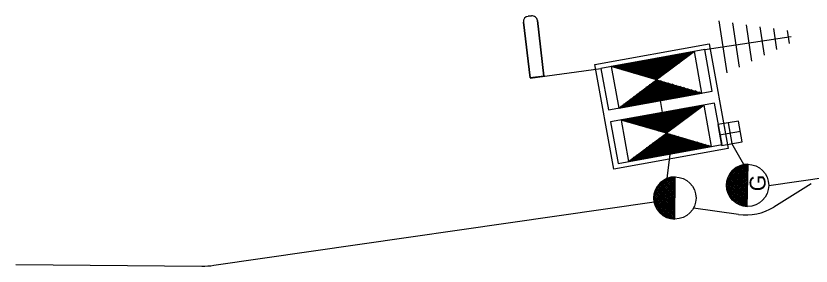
# Model space of a CAD drawing. Extents: x 584850 to 602551, y 145475 to 158627.
# Drawn here: x 585971.5 to 586122.2, y 156296.5 to 156344 of the extents above; entities that cross this region are included whole.
import ezdxf

# ---------------------------------------------------------------- set-up
doc = ezdxf.new("R2010")
doc.units = 0
doc.layers.add('Default', color=7, linetype='Continuous')

msp = doc.modelspace()

# ---------------------------------------------------------------- linework, layer by layer
at = {"layer": 'Default'}
for p, q in [((586106.26, 156333.18), (586104.77, 156343.04)), ((586108.62, 156334.29), (586107.35, 156342.67)), ((586110.98, 156335.4), (586109.94, 156342.31)), ((586113.34, 156336.51), (586112.52, 156341.94)), ((586115.7, 156337.62), (586115.1, 156341.58)), ((586118.06, 156338.73), (586117.69, 156341.21)), ((586102.04, 156337.59), (586118.4, 156340.05)), ((586094.13, 156332.78), (586096.81, 156336.64)), ((586094.74, 156333.23), (586097.14, 156336.7)), ((586095.35, 156333.69), (586097.47, 156336.76)), ((586095.95, 156334.14), (586097.81, 156336.82)), ((586096.56, 156334.6), (586098.14, 156336.88)), ((586098.18, 156335.81), (586096.95, 156336.66)), ((586097.17, 156335.05), (586098.48, 156336.94)), ((586098.38, 156335.96), (586097.28, 156336.72)), ((586098.58, 156336.11), (586097.62, 156336.78)), ((586097.77, 156335.51), (586098.81, 156337)), ((586098.79, 156336.26), (586097.95, 156336.84)), ((586098.99, 156336.42), (586098.29, 156336.9)), ((586098.38, 156335.96), (586099.14, 156337.06)), ((586099.19, 156336.57), (586098.62, 156336.97)), ((586099.39, 156336.72), (586098.95, 156337.03)), ((586098.99, 156336.42), (586099.48, 156337.12)), ((586099.6, 156336.87), (586099.29, 156337.09)), ((586099.6, 156336.87), (586099.81, 156337.18)), ((586099.8, 156337.02), (586099.62, 156337.15)), ((586100, 156337.18), (586099.96, 156337.21)), ((586087.33, 156333.5), (586088.46, 156335.12)), ((586087.57, 156333.43), (586088.79, 156335.18)), ((586087.82, 156333.36), (586089.12, 156335.24)), ((586088.06, 156333.28), (586089.46, 156335.3)), ((586088.3, 156333.21), (586089.79, 156335.36)), ((586088.54, 156333.14), (586090.13, 156335.42)), ((586093.12, 156332.02), (586088.6, 156335.15)), ((586088.79, 156333.07), (586090.46, 156335.48)), ((586093.32, 156332.17), (586088.94, 156335.21)), ((586089.03, 156333), (586090.79, 156335.55)), ((586089.27, 156332.93), (586091.13, 156335.61)), ((586093.52, 156332.32), (586089.27, 156335.27)), ((586089.52, 156332.86), (586091.46, 156335.67)), ((586093.73, 156332.47), (586089.6, 156335.33)), ((586089.76, 156332.79), (586091.8, 156335.73)), ((586093.93, 156332.62), (586089.94, 156335.39)), ((586090, 156332.72), (586092.13, 156335.79)), ((586090.24, 156332.65), (586092.46, 156335.85)), ((586094.13, 156332.78), (586090.27, 156335.45)), ((586090.49, 156332.58), (586092.8, 156335.91)), ((586094.33, 156332.93), (586090.61, 156335.51)), ((586090.73, 156332.5), (586093.13, 156335.97)), ((586094.54, 156333.08), (586090.94, 156335.57)), ((586090.97, 156332.43), (586093.47, 156336.03)), ((586091.22, 156332.36), (586093.8, 156336.09)), ((586094.74, 156333.23), (586091.27, 156335.63)), ((586091.46, 156332.29), (586094.13, 156336.15)), ((586094.94, 156333.38), (586091.61, 156335.69)), ((586091.7, 156332.22), (586094.47, 156336.21)), ((586091.94, 156332.15), (586094.8, 156336.27)), ((586095.14, 156333.53), (586091.94, 156335.75)), ((586092.19, 156332.08), (586095.14, 156336.33)), ((586095.34, 156333.69), (586092.27, 156335.81)), ((586092.43, 156332.01), (586095.47, 156336.39)), ((586095.55, 156333.84), (586092.61, 156335.87)), ((586092.67, 156331.94), (586095.8, 156336.45)), ((586092.92, 156331.87), (586096.14, 156336.51)), ((586095.75, 156333.99), (586092.94, 156335.94)), ((586095.95, 156334.14), (586093.28, 156336)), ((586093.52, 156332.32), (586096.47, 156336.58)), ((586096.15, 156334.29), (586093.61, 156336.06)), ((586096.36, 156334.44), (586093.94, 156336.12)), ((586096.56, 156334.6), (586094.28, 156336.18)), ((586096.76, 156334.75), (586094.61, 156336.24)), ((586096.96, 156334.9), (586094.95, 156336.3)), ((586097.17, 156335.05), (586095.28, 156336.36)), ((586097.37, 156335.2), (586095.61, 156336.42)), ((586097.57, 156335.36), (586095.95, 156336.48)), ((586097.77, 156335.51), (586096.28, 156336.54)), ((586097.98, 156335.66), (586096.62, 156336.6)), ((586068.98, 156332.17), (586082.36, 156334.02)), ((586084.42, 156334.35), (586084.45, 156334.39)), ((586084.91, 156334.21), (586084.59, 156334.42)), ((586084.66, 156334.28), (586084.78, 156334.45)), ((586084.9, 156334.21), (586085.12, 156334.52)), ((586085.63, 156333.99), (586084.93, 156334.48)), ((586085.14, 156334.14), (586085.45, 156334.58)), ((586086.36, 156333.78), (586085.26, 156334.54)), ((586085.39, 156334.06), (586085.78, 156334.64)), ((586087.09, 156333.57), (586085.6, 156334.6)), ((586085.63, 156333.99), (586086.12, 156334.7)), ((586085.87, 156333.92), (586086.45, 156334.76)), ((586087.82, 156333.35), (586085.93, 156334.66)), ((586086.12, 156333.85), (586086.79, 156334.82)), ((586088.55, 156333.14), (586086.26, 156334.72)), ((586086.36, 156333.78), (586087.12, 156334.88)), ((586086.6, 156333.71), (586087.45, 156334.94)), ((586089.27, 156332.93), (586086.6, 156334.78)), ((586086.84, 156333.64), (586087.79, 156335)), ((586090, 156332.72), (586086.93, 156334.84)), ((586087.09, 156333.57), (586088.12, 156335.06)), ((586090.73, 156332.5), (586087.27, 156334.91)), ((586091.46, 156332.29), (586087.6, 156334.97)), ((586092.19, 156332.08), (586087.93, 156335.03)), ((586092.92, 156331.87), (586088.27, 156335.09)), ((586089.02, 156327.09), (586091.7, 156330.96)), ((586089.36, 156327.15), (586092.31, 156331.41)), ((586089.69, 156327.21), (586092.92, 156331.87)), ((586090.02, 156327.27), (586093.16, 156331.8)), ((586090.36, 156327.33), (586093.4, 156331.72)), ((586090.69, 156327.39), (586093.64, 156331.65)), ((586091.03, 156327.46), (586093.89, 156331.58)), ((586094.9, 156328.16), (586091.3, 156330.65)), ((586091.36, 156327.52), (586094.13, 156331.51)), ((586095.23, 156328.22), (586091.5, 156330.8)), ((586091.69, 156327.58), (586094.37, 156331.44)), ((586095.56, 156328.28), (586091.7, 156330.96)), ((586095.9, 156328.34), (586091.9, 156331.11)), ((586092.03, 156327.64), (586094.62, 156331.37)), ((586096.23, 156328.4), (586092.11, 156331.26)), ((586096.57, 156328.46), (586092.31, 156331.41)), ((586092.36, 156327.7), (586094.86, 156331.3)), ((586096.9, 156328.52), (586092.51, 156331.56)), ((586092.7, 156327.76), (586095.1, 156331.23)), ((586097.23, 156328.58), (586092.71, 156331.71)), ((586097.57, 156328.64), (586092.92, 156331.87)), ((586093.03, 156327.82), (586095.34, 156331.16)), ((586093.36, 156327.88), (586095.59, 156331.09)), ((586097.9, 156328.7), (586093.64, 156331.65)), ((586093.7, 156327.94), (586095.83, 156331.01)), ((586094.03, 156328), (586096.07, 156330.94)), ((586098.23, 156328.76), (586094.37, 156331.44)), ((586094.37, 156328.06), (586096.31, 156330.87)), ((586094.7, 156328.12), (586096.56, 156330.8)), ((586095.04, 156328.18), (586096.8, 156330.73)), ((586098.57, 156328.82), (586095.1, 156331.23)), ((586095.37, 156328.24), (586097.04, 156330.66)), ((586098.9, 156328.88), (586095.83, 156331.01)), ((586099.24, 156328.94), (586096.56, 156330.8)), ((586087.69, 156326.85), (586089.27, 156329.13)), ((586088.02, 156326.91), (586089.88, 156329.59)), ((586088.35, 156326.97), (586090.49, 156330.04)), ((586088.69, 156327.03), (586091.09, 156330.5)), ((586091.56, 156327.55), (586089.27, 156329.14)), ((586091.89, 156327.61), (586089.47, 156329.29)), ((586092.22, 156327.67), (586089.68, 156329.44)), ((586092.56, 156327.73), (586089.88, 156329.59)), ((586092.89, 156327.79), (586090.08, 156329.74)), ((586093.23, 156327.85), (586090.28, 156329.89)), ((586093.56, 156327.92), (586090.49, 156330.05)), ((586093.89, 156327.98), (586090.69, 156330.2)), ((586094.23, 156328.04), (586090.89, 156330.35)), ((586094.56, 156328.1), (586091.09, 156330.5)), ((586095.7, 156328.3), (586097.29, 156330.59)), ((586096.04, 156328.36), (586097.53, 156330.52)), ((586096.37, 156328.43), (586097.77, 156330.45)), ((586096.7, 156328.49), (586098.01, 156330.38)), ((586097.04, 156328.55), (586098.26, 156330.3)), ((586099.57, 156329.01), (586097.29, 156330.59)), ((586097.37, 156328.61), (586098.5, 156330.23)), ((586097.71, 156328.67), (586098.74, 156330.16)), ((586099.9, 156329.07), (586098.02, 156330.38)), ((586098.04, 156328.73), (586098.99, 156330.09)), ((586098.38, 156328.79), (586099.23, 156330.02)), ((586098.71, 156328.85), (586099.47, 156329.95)), ((586100.24, 156329.13), (586098.74, 156330.16)), ((586099.04, 156328.91), (586099.71, 156329.88)), ((586099.38, 156328.97), (586099.96, 156329.81)), ((586100.57, 156329.19), (586099.47, 156329.95)), ((586099.71, 156329.03), (586100.2, 156329.74)), ((586100.04, 156329.09), (586100.44, 156329.67)), ((586100.91, 156329.25), (586100.2, 156329.74)), ((586100.38, 156329.15), (586100.69, 156329.6)), ((586100.71, 156329.21), (586100.93, 156329.52)), ((586101.24, 156329.31), (586100.93, 156329.52)), ((586101.05, 156329.27), (586101.17, 156329.45)), ((586101.38, 156329.33), (586101.41, 156329.38)), ((586086.68, 156326.67), (586087.45, 156327.77)), ((586087.02, 156326.73), (586088.05, 156328.22)), ((586088.22, 156326.95), (586087.25, 156327.62)), ((586087.35, 156326.79), (586088.66, 156328.68)), ((586088.55, 156327.01), (586087.45, 156327.77)), ((586088.89, 156327.07), (586087.65, 156327.92)), ((586089.22, 156327.13), (586087.85, 156328.07)), ((586089.55, 156327.19), (586088.06, 156328.22)), ((586089.89, 156327.25), (586088.26, 156328.38)), ((586090.22, 156327.31), (586088.46, 156328.53)), ((586090.56, 156327.37), (586088.66, 156328.68)), ((586090.89, 156327.43), (586088.87, 156328.83)), ((586091.22, 156327.49), (586089.07, 156328.98)), ((586094.04, 156325.65), (586093.63, 156327.93)), ((586085.88, 156326.52), (586085.83, 156326.56)), ((586086.02, 156326.55), (586086.23, 156326.86)), ((586086.21, 156326.58), (586086.03, 156326.71)), ((586086.55, 156326.64), (586086.24, 156326.86)), ((586086.35, 156326.61), (586086.84, 156327.31)), ((586086.88, 156326.7), (586086.44, 156327.01)), ((586087.22, 156326.76), (586086.64, 156327.16)), ((586087.55, 156326.82), (586086.84, 156327.31)), ((586087.88, 156326.89), (586087.04, 156327.47)), ((586093.78, 156322), (586096.64, 156326.13)), ((586094.03, 156321.93), (586096.98, 156326.19)), ((586094.27, 156321.86), (586097.31, 156326.25)), ((586094.51, 156321.79), (586097.64, 156326.31)), ((586094.76, 156321.72), (586097.98, 156326.37)), ((586095.36, 156322.17), (586098.31, 156326.43)), ((586095.97, 156322.63), (586098.65, 156326.49)), ((586098.6, 156324.6), (586096.45, 156326.09)), ((586096.58, 156323.08), (586098.98, 156326.55)), ((586098.81, 156324.75), (586096.79, 156326.15)), ((586099.01, 156324.9), (586097.12, 156326.21)), ((586097.19, 156323.54), (586099.31, 156326.61)), ((586099.21, 156325.06), (586097.45, 156326.27)), ((586097.79, 156323.99), (586099.65, 156326.67)), ((586099.41, 156325.21), (586097.79, 156326.33)), ((586099.61, 156325.36), (586098.12, 156326.39)), ((586098.4, 156324.45), (586099.98, 156326.73)), ((586099.82, 156325.51), (586098.46, 156326.45)), ((586100.02, 156325.66), (586098.79, 156326.51)), ((586099.01, 156324.9), (586100.32, 156326.79)), ((586100.22, 156325.81), (586099.12, 156326.58)), ((586100.42, 156325.97), (586099.46, 156326.64)), ((586099.62, 156325.36), (586100.65, 156326.85)), ((586100.63, 156326.12), (586099.79, 156326.7)), ((586100.83, 156326.27), (586100.13, 156326.76)), ((586100.22, 156325.81), (586100.98, 156326.91)), ((586101.03, 156326.42), (586100.46, 156326.82)), ((586101.23, 156326.57), (586100.79, 156326.88)), ((586100.83, 156326.27), (586101.32, 156326.97)), ((586101.44, 156326.72), (586101.13, 156326.94)), ((586101.44, 156326.73), (586101.65, 156327.03)), ((586101.64, 156326.88), (586101.46, 156327)), ((586101.84, 156327.03), (586101.8, 156327.06)), ((586087.71, 156323.78), (586088.29, 156324.61)), ((586087.96, 156323.7), (586088.63, 156324.67)), ((586090.39, 156322.99), (586088.1, 156324.58)), ((586088.2, 156323.63), (586088.96, 156324.73)), ((586088.44, 156323.56), (586089.29, 156324.79)), ((586091.11, 156322.78), (586088.44, 156324.64)), ((586088.68, 156323.49), (586089.63, 156324.85)), ((586091.84, 156322.57), (586088.77, 156324.7)), ((586088.93, 156323.42), (586089.96, 156324.91)), ((586092.57, 156322.36), (586089.11, 156324.76)), ((586089.17, 156323.35), (586090.3, 156324.97)), ((586089.41, 156323.28), (586090.63, 156325.03)), ((586093.3, 156322.14), (586089.44, 156324.82)), ((586089.66, 156323.21), (586090.96, 156325.1)), ((586094.03, 156321.93), (586089.77, 156324.88)), ((586089.9, 156323.14), (586091.3, 156325.16)), ((586094.76, 156321.72), (586090.11, 156324.94)), ((586090.14, 156323.07), (586091.63, 156325.22)), ((586090.38, 156323), (586091.97, 156325.28)), ((586094.96, 156321.87), (586090.44, 156325)), ((586090.63, 156322.92), (586092.3, 156325.34)), ((586095.16, 156322.02), (586090.78, 156325.06)), ((586090.87, 156322.85), (586092.63, 156325.4)), ((586091.11, 156322.78), (586092.97, 156325.46)), ((586095.36, 156322.17), (586091.11, 156325.12)), ((586091.36, 156322.71), (586093.3, 156325.52)), ((586095.57, 156322.33), (586091.44, 156325.18)), ((586091.6, 156322.64), (586093.64, 156325.58)), ((586095.77, 156322.48), (586091.78, 156325.24)), ((586091.84, 156322.57), (586093.97, 156325.64)), ((586092.08, 156322.5), (586094.3, 156325.7)), ((586095.97, 156322.63), (586092.11, 156325.3)), ((586092.33, 156322.43), (586094.64, 156325.76)), ((586096.17, 156322.78), (586092.45, 156325.36)), ((586092.57, 156322.36), (586094.97, 156325.82)), ((586096.38, 156322.93), (586092.78, 156325.42)), ((586092.81, 156322.29), (586095.31, 156325.88)), ((586093.06, 156322.22), (586095.64, 156325.94)), ((586096.58, 156323.08), (586093.11, 156325.49)), ((586093.3, 156322.14), (586095.97, 156326)), ((586096.78, 156323.24), (586093.45, 156325.55)), ((586093.54, 156322.07), (586096.31, 156326.06)), ((586096.98, 156323.39), (586093.78, 156325.61)), ((586097.19, 156323.54), (586094.11, 156325.67)), ((586097.39, 156323.69), (586094.45, 156325.73)), ((586097.59, 156323.84), (586094.78, 156325.79)), ((586097.79, 156323.99), (586095.12, 156325.85)), ((586098, 156324.15), (586095.45, 156325.91)), ((586098.2, 156324.3), (586095.78, 156325.97)), ((586098.4, 156324.45), (586096.12, 156326.03)), ((586086.26, 156324.2), (586086.29, 156324.25)), ((586086.75, 156324.06), (586086.43, 156324.27)), ((586086.5, 156324.13), (586086.62, 156324.31)), ((586086.74, 156324.06), (586086.96, 156324.37)), ((586087.47, 156323.85), (586086.77, 156324.33)), ((586086.98, 156323.99), (586087.29, 156324.43)), ((586088.2, 156323.63), (586087.1, 156324.39)), ((586087.23, 156323.92), (586087.62, 156324.49)), ((586088.93, 156323.42), (586087.44, 156324.46)), ((586087.47, 156323.85), (586087.96, 156324.55)), ((586089.66, 156323.21), (586087.77, 156324.52)), ((586106.47, 156323.7), (586107.15, 156319.76)), ((586091.53, 156317.07), (586094.76, 156321.72)), ((586091.87, 156317.13), (586095, 156321.65)), ((586092.2, 156317.19), (586095.24, 156321.58)), ((586099.07, 156318.43), (586094.55, 156321.57)), ((586099.41, 156318.49), (586094.76, 156321.72)), ((586108.78, 156322.07), (586104.84, 156321.38)), ((586090.53, 156316.88), (586092.93, 156320.35)), ((586090.86, 156316.94), (586093.54, 156320.81)), ((586091.2, 156317.01), (586094.15, 156321.26)), ((586092.53, 156317.25), (586095.48, 156321.51)), ((586095.73, 156317.83), (586092.53, 156320.05)), ((586096.07, 156317.89), (586092.73, 156320.2)), ((586092.87, 156317.31), (586095.73, 156321.43)), ((586096.4, 156317.95), (586092.93, 156320.35)), ((586096.74, 156318.01), (586093.14, 156320.5)), ((586093.2, 156317.37), (586095.97, 156321.36)), ((586097.07, 156318.07), (586093.34, 156320.66)), ((586093.53, 156317.43), (586096.21, 156321.29)), ((586097.4, 156318.13), (586093.54, 156320.81)), ((586097.74, 156318.19), (586093.74, 156320.96)), ((586093.87, 156317.49), (586096.46, 156321.22)), ((586098.07, 156318.25), (586093.95, 156321.11)), ((586098.41, 156318.31), (586094.15, 156321.26)), ((586094.2, 156317.55), (586096.7, 156321.15)), ((586098.74, 156318.37), (586094.35, 156321.42)), ((586094.54, 156317.61), (586096.94, 156321.08)), ((586094.87, 156317.67), (586097.18, 156321.01)), ((586095.21, 156317.73), (586097.43, 156320.94)), ((586099.74, 156318.56), (586095.48, 156321.51)), ((586095.54, 156317.79), (586097.67, 156320.87)), ((586095.87, 156317.85), (586097.91, 156320.8)), ((586100.08, 156318.62), (586096.21, 156321.29)), ((586096.21, 156317.91), (586098.16, 156320.73)), ((586096.54, 156317.97), (586098.4, 156320.65)), ((586096.88, 156318.04), (586098.64, 156320.58)), ((586100.41, 156318.68), (586096.94, 156321.08)), ((586097.21, 156318.1), (586098.88, 156320.51)), ((586097.54, 156318.16), (586099.13, 156320.44)), ((586100.74, 156318.74), (586097.67, 156320.87)), ((586097.88, 156318.22), (586099.37, 156320.37)), ((586098.21, 156318.28), (586099.61, 156320.3)), ((586101.08, 156318.8), (586098.4, 156320.65)), ((586098.55, 156318.34), (586099.86, 156320.23)), ((586098.88, 156318.4), (586100.1, 156320.16)), ((586101.41, 156318.86), (586099.13, 156320.44)), ((586099.21, 156318.46), (586100.34, 156320.09)), ((586101.74, 156318.92), (586099.86, 156320.23)), ((586089.53, 156316.7), (586091.11, 156318.99)), ((586089.86, 156316.76), (586091.72, 156319.44)), ((586090.2, 156316.82), (586092.33, 156319.9)), ((586092.73, 156317.28), (586090.71, 156318.68)), ((586093.06, 156317.34), (586090.91, 156318.84)), ((586093.4, 156317.4), (586091.11, 156318.99)), ((586093.73, 156317.47), (586091.31, 156319.14)), ((586094.06, 156317.53), (586091.52, 156319.29)), ((586094.4, 156317.59), (586091.72, 156319.44)), ((586094.73, 156317.65), (586091.92, 156319.6)), ((586095.07, 156317.71), (586092.12, 156319.75)), ((586095.4, 156317.77), (586092.33, 156319.9)), ((586099.55, 156318.52), (586100.58, 156320.02)), ((586099.88, 156318.58), (586100.83, 156319.94)), ((586100.22, 156318.64), (586101.07, 156319.87)), ((586100.55, 156318.7), (586101.31, 156319.8)), ((586102.08, 156318.98), (586100.58, 156320.02)), ((586100.88, 156318.76), (586101.55, 156319.73)), ((586101.22, 156318.82), (586101.8, 156319.66)), ((586102.41, 156319.04), (586101.31, 156319.8)), ((586101.55, 156318.88), (586102.04, 156319.59)), ((586101.89, 156318.94), (586102.28, 156319.52)), ((586102.75, 156319.1), (586102.04, 156319.59)), ((586102.22, 156319.01), (586102.53, 156319.45)), ((586102.55, 156319.07), (586102.77, 156319.38)), ((586103.08, 156319.16), (586102.77, 156319.38)), ((586102.89, 156319.13), (586103.01, 156319.31)), ((586103.22, 156319.19), (586103.25, 156319.24)), ((586109.46, 156315.78), (586107.15, 156319.76)), ((586088.19, 156316.46), (586088.68, 156317.17)), ((586088.53, 156316.52), (586089.29, 156317.62)), ((586089.39, 156316.68), (586088.68, 156317.17)), ((586088.86, 156316.58), (586089.9, 156318.08)), ((586089.72, 156316.74), (586088.89, 156317.32)), ((586090.06, 156316.8), (586089.09, 156317.47)), ((586089.19, 156316.64), (586090.5, 156318.53)), ((586090.39, 156316.86), (586089.29, 156317.62)), ((586090.73, 156316.92), (586089.49, 156317.77)), ((586091.06, 156316.98), (586089.69, 156317.93)), ((586091.39, 156317.04), (586089.9, 156318.08)), ((586091.73, 156317.1), (586090.1, 156318.23)), ((586092.06, 156317.16), (586090.3, 156318.38)), ((586092.4, 156317.22), (586090.5, 156318.53)), ((586094.9, 156313.15), (586095.47, 156317.78)), ((586087.72, 156316.37), (586087.67, 156316.41)), ((586087.86, 156316.4), (586088.07, 156316.71)), ((586088.05, 156316.44), (586087.87, 156316.56)), ((586088.39, 156316.5), (586088.08, 156316.71)), ((586088.72, 156316.56), (586088.28, 156316.86)), ((586089.06, 156316.62), (586088.48, 156317.02)), ((586110.15, 156315.84), (586106.16, 156312)), ((586110.22, 156315.57), (586106.17, 156311.67)), ((586109.78, 156315.81), (586106.2, 156312.37)), ((586109.37, 156315.75), (586106.26, 156312.76)), ((586108.91, 156315.64), (586106.42, 156313.24)), ((586108.85, 156315.62), (586110.2, 156314.22)), ((586109.11, 156315.69), (586110.2, 156314.56)), ((586109.38, 156315.76), (586110.21, 156314.9)), ((586109.67, 156315.8), (586110.22, 156315.24)), ((586109.98, 156315.82), (586110.22, 156315.57)), ((586110.08, 156307.84), (586110.23, 156315.84)), ((586110.18, 156315.84), (586110.23, 156315.8)), ((586110.22, 156315.24), (586106.19, 156311.35)), ((586110.21, 156314.9), (586106.24, 156311.07)), ((586110.2, 156314.56), (586106.3, 156310.79)), ((586110.2, 156314.22), (586106.38, 156310.54)), ((586108.29, 156315.38), (586106.71, 156313.86)), ((586106.91, 156314.17), (586110.13, 156310.82)), ((586107.06, 156314.36), (586110.14, 156311.16)), ((586107.21, 156314.55), (586110.15, 156311.5)), ((586107.39, 156314.71), (586110.15, 156311.84)), ((586107.56, 156314.88), (586110.16, 156312.18)), ((586107.75, 156315.03), (586110.17, 156312.52)), ((586107.95, 156315.16), (586110.17, 156312.86)), ((586108.16, 156315.3), (586110.18, 156313.2)), ((586108.38, 156315.42), (586110.18, 156313.54)), ((586108.61, 156315.52), (586110.19, 156313.88)), ((586096.36, 156313.44), (586092.4, 156309.57)), ((586096.43, 156313.18), (586092.41, 156309.24)), ((586096.43, 156312.84), (586092.43, 156308.92)), ((586095.98, 156313.41), (586092.44, 156309.94)), ((586095.58, 156313.35), (586092.49, 156310.33)), ((586095.12, 156313.23), (586092.65, 156310.81)), ((586094.5, 156312.97), (586092.93, 156311.43)), ((586093.96, 156312.61), (586096.4, 156310.12)), ((586094.16, 156312.75), (586096.4, 156310.46)), ((586094.37, 156312.88), (586096.41, 156310.8)), ((586094.59, 156313), (586096.41, 156311.14)), ((586094.82, 156313.11), (586096.41, 156311.48)), ((586095.06, 156313.21), (586096.42, 156311.82)), ((586095.32, 156313.28), (586096.42, 156312.16)), ((586095.59, 156313.35), (586096.42, 156312.5)), ((586095.88, 156313.4), (586096.43, 156312.84)), ((586096.19, 156313.42), (586096.43, 156313.18)), ((586096.35, 156305.44), (586096.43, 156313.44)), ((586096.39, 156313.44), (586096.43, 156313.4)), ((586106.26, 156312.77), (586110.1, 156308.79)), ((586106.35, 156313.03), (586110.1, 156309.13)), ((586106.43, 156313.28), (586110.11, 156309.47)), ((586110.19, 156313.88), (586106.48, 156310.3)), ((586106.53, 156313.52), (586110.11, 156309.81)), ((586110.18, 156313.54), (586106.58, 156310.06)), ((586106.65, 156313.75), (586110.12, 156310.15)), ((586110.18, 156313.2), (586106.7, 156309.85)), ((586106.77, 156313.97), (586110.13, 156310.48)), ((586110.17, 156312.86), (586106.83, 156309.64)), ((586110.17, 156312.52), (586106.97, 156309.44)), ((586114.06, 156312.83), (586113.96, 156312.78)), ((586096.42, 156312.5), (586092.49, 156308.64)), ((586096.42, 156312.16), (586092.54, 156308.36)), ((586096.42, 156311.82), (586092.63, 156308.11)), ((586096.41, 156311.48), (586092.73, 156307.87)), ((586092.76, 156311.1), (586096.37, 156307.41)), ((586096.41, 156311.14), (586092.83, 156307.63)), ((586092.88, 156311.32), (586096.37, 156307.75)), ((586092.99, 156311.54), (586096.38, 156308.09)), ((586093.13, 156311.74), (586096.38, 156308.43)), ((586093.28, 156311.94), (586096.38, 156308.76)), ((586093.43, 156312.13), (586096.39, 156309.1)), ((586093.6, 156312.29), (586096.39, 156309.44)), ((586093.78, 156312.46), (586096.4, 156309.78)), ((586106.17, 156312.17), (586110.08, 156308.11)), ((586106.17, 156311.83), (586110, 156307.85)), ((586106.17, 156311.47), (586109.63, 156307.88)), ((586106.22, 156312.47), (586110.09, 156308.45)), ((586106.25, 156311.05), (586109.23, 156307.96)), ((586110.16, 156312.18), (586107.12, 156309.25)), ((586110.15, 156311.84), (586107.28, 156309.07)), ((586110.15, 156311.5), (586107.45, 156308.91)), ((586110.14, 156311.16), (586107.64, 156308.75)), ((586122.18, 156312.13), (586115.12, 156307.73)), ((586092.41, 156309.74), (586096.35, 156305.71)), ((586092.45, 156310.04), (586096.36, 156306.05)), ((586092.49, 156310.34), (586096.36, 156306.39)), ((586092.58, 156310.6), (586096.36, 156306.73)), ((586092.66, 156310.86), (586096.37, 156307.07)), ((586096.41, 156310.8), (586092.96, 156307.42)), ((586096.4, 156310.46), (586093.08, 156307.21)), ((586096.4, 156310.12), (586093.22, 156307.01)), ((586096.4, 156309.78), (586093.38, 156306.83)), ((586106.37, 156310.58), (586108.75, 156308.11)), ((586106.64, 156309.96), (586108.13, 156308.41)), ((586110.13, 156310.82), (586107.82, 156308.6)), ((586110.13, 156310.48), (586108.03, 156308.47)), ((586110.12, 156310.15), (586108.25, 156308.34)), ((586110.11, 156309.81), (586108.47, 156308.22)), ((586092.41, 156309.4), (586096.27, 156305.45)), ((586092.42, 156309.04), (586095.9, 156305.48)), ((586092.49, 156308.62), (586095.5, 156305.56)), ((586092.62, 156308.15), (586095.02, 156305.7)), ((586096.39, 156309.44), (586093.54, 156306.65)), ((586096.39, 156309.1), (586093.71, 156306.49)), ((586096.38, 156308.76), (586093.9, 156306.33)), ((586096.38, 156308.43), (586094.09, 156306.18)), ((586096.38, 156308.09), (586094.3, 156306.05)), ((586110.11, 156309.47), (586108.71, 156308.12)), ((586110.1, 156309.13), (586108.96, 156308.03)), ((586110.1, 156308.79), (586109.24, 156307.96)), ((586110.09, 156308.45), (586109.52, 156307.9)), ((586110.08, 156308.11), (586109.82, 156307.86)), ((586092.89, 156307.53), (586094.39, 156305.99)), ((586096.37, 156307.75), (586094.51, 156305.93)), ((586096.37, 156307.41), (586094.73, 156305.81)), ((586096.37, 156307.07), (586094.98, 156305.71)), ((586096.36, 156306.73), (586095.23, 156305.62)), ((586108.42, 156306.32), (586099.91, 156307.54)), ((586110.08, 156307.84), (586110.08, 156307.84)), ((586110.08, 156307.84), (586110.08, 156307.84)), ((586096.36, 156306.39), (586095.51, 156305.55)), ((586096.36, 156306.05), (586095.79, 156305.5)), ((586096.35, 156305.71), (586096.09, 156305.46)), ((586096.35, 156305.44), (586096.35, 156305.45)), ((586096.35, 156305.44), (586096.35, 156305.45)), ((585971.53, 156296.84), (586006.77, 156296.52))]:
    msp.add_line(p, q, dxfattribs=at)
for points in [[(586070.32, 156343.11), (586071.57, 156332.54), (586068.93, 156332.23), (586067.68, 156342.79)], [(586067.68, 156342.79), (586068.93, 156332.23), (586071.57, 156332.54), (586070.32, 156343.11)], [(586068.55, 156343.91), (586069.21, 156343.98)], [(586069.21, 156343.98), (586068.55, 156343.91)], [(586114.15, 156311.83), (586193.73, 156323.3)], [(586009.05, 156296.67), (586092.46, 156308.7)]]:
    msp.add_lwpolyline(points, dxfattribs=at)
for points in [[(586084.81, 156314.92), (586081.22, 156334.74), (586102.86, 156338.67), (586106.46, 156318.84)], [(586102.04, 156337.59), (586082.36, 156334.02), (586083.79, 156326.14), (586103.47, 156329.71)], [(586100.07, 156337.23), (586084.33, 156334.37), (586085.76, 156326.5), (586101.5, 156329.36)], [(586100.07, 156337.23), (586092.92, 156331.87), (586084.33, 156334.37)], [(586101.5, 156329.36), (586085.75, 156326.5), (586092.92, 156331.87)], [(586103.88, 156327.44), (586084.2, 156323.87), (586085.63, 156316), (586105.31, 156319.57)], [(586101.91, 156327.08), (586086.17, 156324.23), (586087.6, 156316.35), (586103.34, 156319.21)], [(586101.91, 156327.08), (586094.76, 156321.72), (586086.17, 156324.23)], [(586104.5, 156323.36), (586105.18, 156319.41), (586109.12, 156320.1), (586108.44, 156324.04)], [(586103.34, 156319.21), (586087.59, 156316.35), (586094.76, 156321.72)]]:
    msp.add_lwpolyline(points, close=True, dxfattribs=at)
for centre in [(586110.15, 156311.84), (586096.39, 156309.44)]:
    msp.add_circle(centre, 4, dxfattribs=at)
for centre, radius, start, end in [((586068.67, 156342.91), 1, 96.7729, 186.7729), ((586068.67, 156342.91), 1, 96.7729, 186.7729), ((586069.33, 156342.99), 1, 6.7729, 96.7729), ((586069.33, 156342.99), 1, 6.7729, 96.7729), ((586110.15, 156311.84), 4, 88.9257, 268.9257), ((586096.39, 156309.44), 4, 89.3846, 269.3846), ((586109.84, 156316.22), 10, 261.8672, 301.9166), ((586006.91, 156311.52), 15, 269.4712, 278.2052)]:
    msp.add_arc(centre, radius, start, end, dxfattribs=at)

# ---------------------------------------------------------------- texts
msp.add_text('G', height=3, rotation=89.3623, dxfattribs=at).set_placement((586113.53, 156310.71))

doc.saveas('drawing.dxf')
